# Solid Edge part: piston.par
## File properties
Author: Robert a Rhodes jr
Template: normal.par
Last saved by: CADCIM
Revision: 20
Application: Solid Edge
Accuracy: 0.99
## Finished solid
Body 1: solid body, 42 faces, 58 edges, 16 vertices.
  Faces by surface: cylinder 21, plane 20, torus 1
  Edges by curve: circle 40, intersection 10, line 8
Bounding box of the edges (mm; curved faces can reach further): 93.000 x 93.000 x 66.000, from (-46.5, -46.5, -46) to (46.5, 46.5, 20).
Cylindrical faces by radius (mm): R10 x2, R15 x2, R19 x2, R37 x2, R38.5 x2, R42.5 x5, R46.5 x6
Toroidal faces (ring radius, tube radius in mm): R-5.5431 r189 x1
Planar faces by outward normal: +y 2, +z 7, -y 2, -z 9
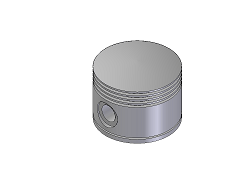
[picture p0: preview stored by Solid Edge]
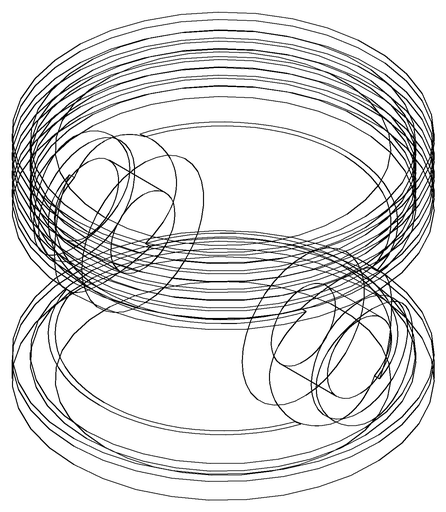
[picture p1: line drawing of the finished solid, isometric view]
